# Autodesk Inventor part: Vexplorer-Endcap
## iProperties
Created: 2007-10
Part Number: Vexplorer-Endcap
Document SubType Name: Modeling
Material: ABS Plastic
Density: 1.06 g/cm^3
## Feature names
1. Base1
